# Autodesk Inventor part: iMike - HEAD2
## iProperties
Shininess: 64.0
Length Units: 11272
Angle Units: 11279
Time Units: 11290
Mass Units: 11286
Length Display Precision: 3
Angle Display Precision: 2
Compacted: True
Part Number: iMike - HEAD2
Document SubType Name: Modeling
Created: 2003-07
Designer: MVF
Manufacturer: Standard
Standards Organization: Custom
Density: 0.0
Volumn: 0.0
Area: 0.0
PropertySet Name: Model Information
Control State: 0
Master: False
Checked Out: False
Author: MVF
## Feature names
1. Revolution1
2. Extrusion1
3. Extrusion2
4. Mirror1
5. Fillet1
6. Revolution2
7. Extrusion3
8. Fillet2
9. Extrusion4
